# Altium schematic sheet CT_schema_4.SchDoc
size 176 x 147 mm
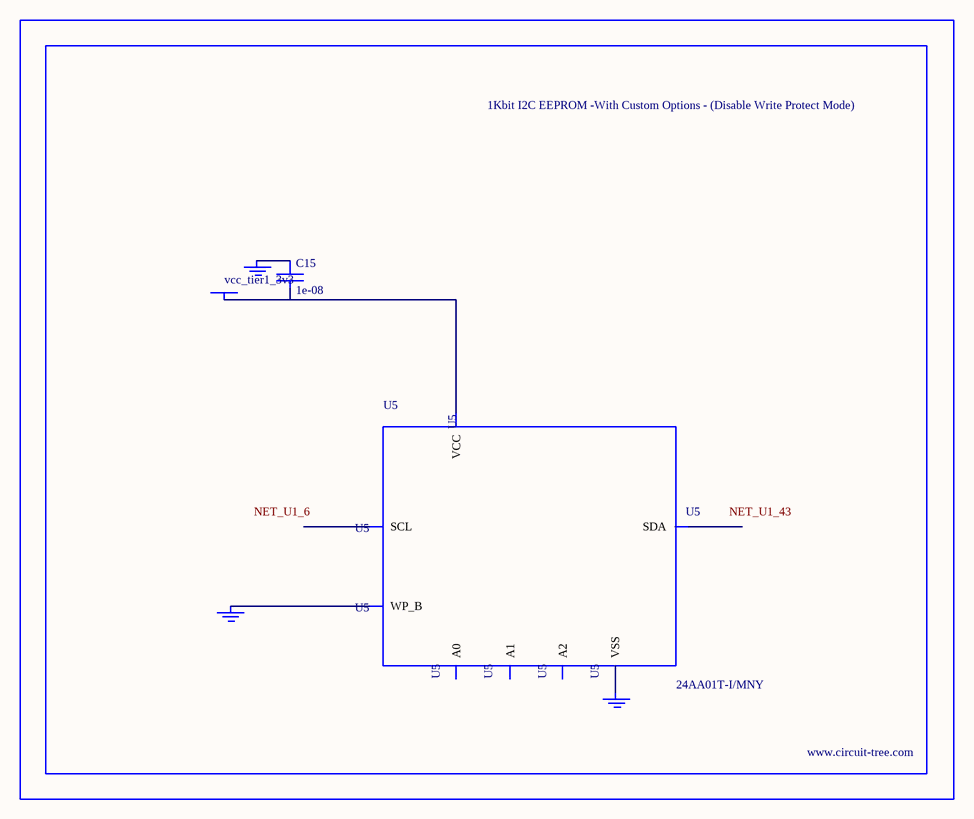
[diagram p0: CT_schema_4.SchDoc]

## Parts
BORDER3  (no value)
C15  1e-08  [C0402]
GND_INSTANCE_3_0  (no value)
GND_INSTANCE_3_1  (no value)
GND_INSTANCE_3_2  (no value)
POWER_INSTANCE_3_0  vcc_tier1_3v3
U5  24AA01T-I/MNY  [TDFN-8/6MM]

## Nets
NetC15_1: C15.1 GND_INSTANCE_3_1.0(GND)
NetC15_2: C15.2 POWER_INSTANCE_3_0.0(PWR) U5.8(VCC)
NetGND_INSTANCE_3_0_0: GND_INSTANCE_3_0.0(GND) U5.7(WP_B)
NetGND_INSTANCE_3_2_0: GND_INSTANCE_3_2.0(GND) U5.4(VSS)

Not connected (* = marked no-connect by the designer): U5 1(A0) 2(A1) 3(A2) 5(SDA) 6(SCL)

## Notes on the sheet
- Labels drawn without touching a wire or pin: NET_U1_6, NET_U1_43

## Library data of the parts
BORDER3 = BORDER_PAGE3
C15 = C0402C103K3RAC
GND_INSTANCE_3_0-GND_INSTANCE_3_2 = GND
POWER_INSTANCE_3_0 = PWR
